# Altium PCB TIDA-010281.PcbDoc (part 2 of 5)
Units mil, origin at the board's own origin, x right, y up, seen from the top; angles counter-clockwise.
Board outline 3455.86 x 1121.8 mil, 8 copper layers (Top Layer, GND1, Sig1, PWR1, PWR2, Sig2, GND2, Bottom Layer), stack 59.155 mil thick; 291 components, 180 nets, 941 pads, 539 vias.
Unrouted connection lines stored in the file: 41.
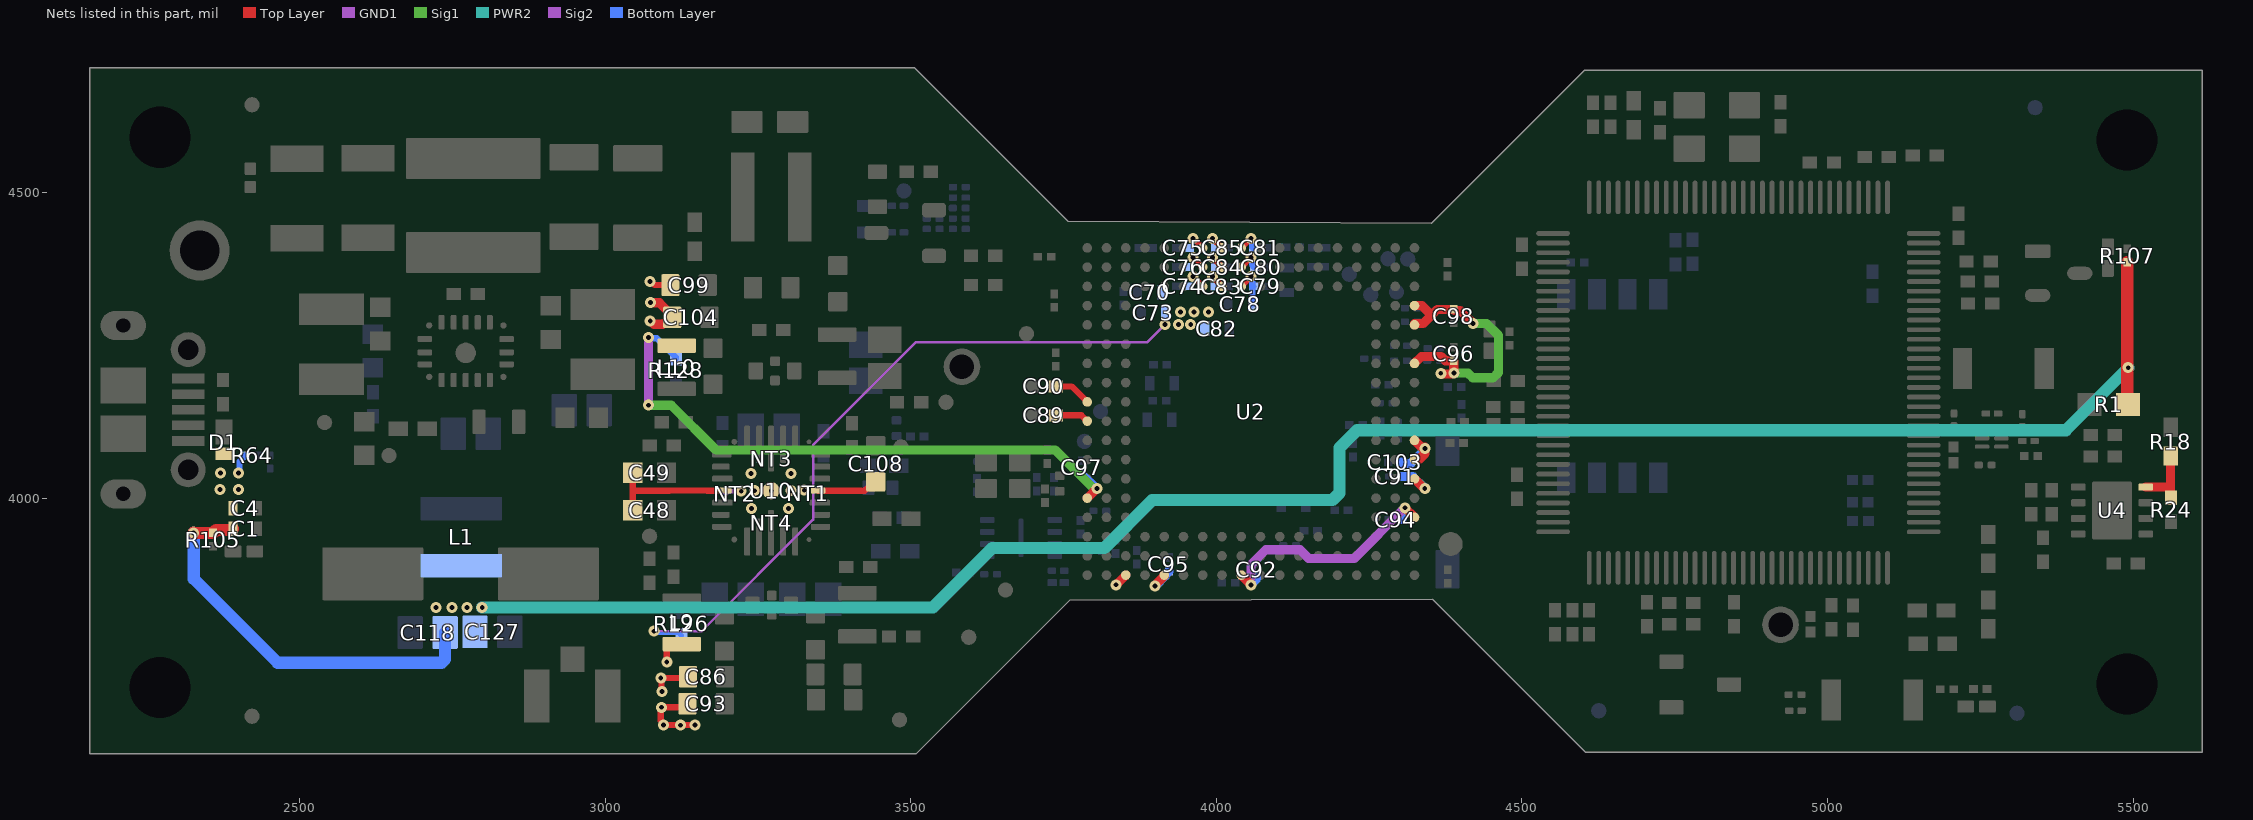
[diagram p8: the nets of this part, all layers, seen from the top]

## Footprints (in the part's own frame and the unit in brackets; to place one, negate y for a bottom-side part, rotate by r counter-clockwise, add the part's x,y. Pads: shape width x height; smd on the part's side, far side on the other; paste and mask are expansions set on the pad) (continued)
FP-4953_HDR1-MFG [mm]
  round 2.5 hole 1.65 paste-1000 mask+0: 1(0,0)
  body extent -1.42,-1.35 1.42,1.35, height 0.25
FP-74438366010_SMT_IND_5MM4_5MM4-MFG [mm]
  rrect6% 1.7x5.6 smd paste+0 mask+0: 1(-1.95,0) 2(1.95,0)
  silkscreen extent -3.47,-2.8 0.72,2.8, body extent -2.7,-2.7 2.7,2.7, height 2.1
FP-885012106005_0603-MFG [mm]
  rrect13% 0.8x0.8 smd paste+0 mask+0: 1(-0.75,0) 2(0.75,0)
  silkscreen extent -0.9,-0.77 0.9,0.77, body extent -1.25,-0.6 1.25,0.6, height 0.25
FP-A767KS336M1KLAE045_RADIAL-MFG [mm]
  rrect5% 4.2x2.2 smd paste+0 mask+0: 1(-3.65,0) 2(3.65,0)
  silkscreen extent -6.42,-4.25 4.25,4.25, body extent -4.5,-4.15 4.5,4.15, height 12.5
FP-ABS05W-32.768KHZ-D-2-T_XTAL_SMT_1MM6_1MM0-MFG [mm]
  rrect20% 0.5x1 smd paste+0 mask+0: 1(-0.55,0) 2(0.55,0)
  body extent -0.8,-0.5 0.8,0.5, height 0.5
FP-BSS123-7-F_SOT23-IPC_C [mm]
  rrect18% 1.059x0.547 smd paste+0 mask+0: 1(-0.877,0.915)
  rrect100% 1.059x0.547 smd paste+0 mask+0: 2(-0.877,-0.915) 3(0.877,0)
  body extent -1.51,-1.55 1.51,1.55, height 0.25
FP-CGA3E1X7R1C105M080AC_0603-IPC_C [mm]
  rrect18% 0.556x1.006 smd paste+0 mask+0: 1(-0.825,0) 2(0.825,0)
  silkscreen extent -0.25,-0.55 0.25,0.55, body extent -0.8,-0.4 0.8,0.4, height 1.1
FP-CHS-01TA_SMT_SW_5MM4_2MM5-MFG [mm]
  rrect10% 1.6x1 smd paste+0 mask+0: 1(-2.54,0) 2(2.54,0)
  body extent -2.8,-1.25 2.8,1.25, height 2.5
FP-CL03A105MO3NRNH_0201-IPC_C [mil]
  rrect33% 15.83x11.94 smd paste+0 mask+0: 1(-9.87,0) 2(9.87,0)
  body extent -12,-6 12,6, height 15
FP-CX2016DB40000D0FLJCC_SMT_2MM0_1MM6-MFG [mm]
  rrect13% 0.9x0.8 smd paste+0 mask+0: 1(-0.7,-0.55) 2(0.7,-0.55) 3(0.7,0.55) 4(-0.7,0.55)
  body extent -1.25,-1.05 1.25,1.05, height 0.25
FP-ECS-160-8-33Q-RES-TR_SMT4_3MM2_2MM5-MFG [mm]
  rrect9% 1.3x1.1 smd paste+0 mask+0: 1(-1.15,-0.9) 2(1.15,-0.9) 3(1.15,0.9) 4(-1.15,0.9)
  silkscreen extent -2.48,-1.3 0.13,1.3, body extent -1.9,-1.55 1.9,1.55, height 0.25
FP-GRM21BD72A225ME01K_0805-IPC_C [mil]
  rrect9% 41.52x53.39 smd paste+0 mask+0: 1(-28.57,0) 2(28.57,0)
  silkscreen extent -49,-44 49,44, body extent -39,-25 39,25, height 57
FP-GRM32EC81C476KE15K_1210-MFG [mm]
  rrect9% 1.1x2.05 smd paste+0 mask+0: 1(-1.65,0) 2(1.65,0)
  silkscreen extent -0.72,-1.35 0.72,1.35, body extent -1.6,-1.25 1.6,1.25, height 2.7
"FP-GRM033R6YA104KE14D_0201 (0603 Metric)-IPC_C" [mil]
  rrect38% 13.94x10.34 smd paste+0 mask+0: 1(-10.01,0) 2(10.01,0)
  body extent -21,-10 21,10, height 10
FP-GRM155R71E104KE14J_0402-IPC_C [mil]
  rrect21% 20.29x18.6 smd paste+0 mask+0: 1(-14.9,0) 2(14.9,0)
  silkscreen extent -25,-27 25,27, body extent -29,-15 29,15, height 10
FP-GRM187R60J226ME15D_0603-MFG [mm]
  rrect13% 0.75x0.9 smd paste+0 mask+0: 1(-0.775,0) 2(0.775,0)
  silkscreen extent 0,-0.5 0,0.5, body extent -1.25,-0.6 1.25,0.6, height 0.25
FP-HCJ0603ZT0R00_0603-MFG [mm]
  rrect11% 1.3x0.92 smd paste+0 mask+0: 1(-0.95,0) 2(0.95,0)
  silkscreen extent -0.9,-0.83 0.9,0.83, body extent -1.7,-0.63 1.7,0.63, height 0.25
FP-NFM18HC105C1C3D_0603-MFG [mm]
  rrect17% 0.6x0.7 smd paste+0 mask+0: 1(-0.8,0) 3(0.8,0)
  rrect25% 0.4x0.4 smd paste+0 mask+0: 2(0,0.4) 2(0,-0.4)
  silkscreen extent -1.78,-0.97 0.85,0.97, body extent -1.2,-0.7 1.2,0.7, height 0.25
"FP-RC0201JR-070RL_0201 (0603 METRIC)-IPC_C" [mil]
  rrect38% 13.94x10.34 smd paste+0 mask+0: 1(-10.01,0) 2(10.01,0)
  body extent -12,-6 12,6, height 10
"FP-RC0201JR-070RL_0201 (0603 Metric)-MFG" [mm]
  rrect29% 0.35x0.4 smd paste+0 mask+0: 1(-0.325,0) 2(0.325,0)
  body extent -0.3,-0.15 0.3,0.15, height 0.26
FP-RC0402FR-0710KL_0402-MFG [mm]
  rrect20% 0.5x0.6 smd paste+0 mask+0: 1(-0.5,0) 2(0.5,0)
  silkscreen extent -0.5,-0.67 0.5,0.67, body extent -0.5,-0.25 0.5,0.25, height 0.4
FP-RR0306P-103-D_0201-IPC_C#1 [mil]
  rrect37% 13.31x10.73 smd paste+0 mask+0: 1(-10.52,0) 2(10.52,0)
  body extent -12,-6 12,6, height 10
FP-RR0306P-103-D_0201-IPC_C#2 [mil]
  rrect38% 13.94x10.34 smd paste+0 mask+0: 1(-10.52,0)
  rrect37% 13.31x10.73 smd paste+0 mask+0: 2(10.52,0)
  body extent -12,-6 12,6, height 10
FP-XGL4030-152MEC_SMT2_4MM0_4MM0-MFG [mm]
  rrect10% 0.98x3.4 smd paste+0 mask+0: 1(-1.185,0) 2(1.185,0)
  silkscreen extent -2.75,-2.15 2.15,2.15, body extent -2,-2 2,2, height 3.1
MHNP_2-5 [mil]
  round 95 hole 100 unplated mask+5.5: ""(0,0)
  Keep-Out Layer circle w1: c0,0 r100
Net-Tie_50milWide_30milLong [mil] "50mil net tie, no solder mask opening, no solder paste"
  rect 30x50 on Mid1 paste-20 mask-20: 1(-15,0) 2(15,0)
PDT0128A [mm] "Thin QFP, 128-Leads, Body 14x14mm, Pitch 0.4mm"
  oval 1.4x0.2 smd: 1(-7.7,6.2) 2(-7.7,5.8) 3(-7.7,5.4) 4(-7.7,5) 5(-7.7,4.6) 6(-7.7,4.2) 7(-7.7,3.8) 8(-7.7,3.4) 9(-7.7,3) 10(-7.7,2.6) 11(-7.7,2.2) 12(-7.7,1.8) 13(-7.7,1.4) 14(-7.7,1) 15(-7.7,0.6) 16(-7.7,0.2) 17(-7.7,-0.2) 18(-7.7,-0.6) 19(-7.7,-1) 20(-7.7,-1.4) 21(-7.7,-1.8) 22(-7.7,-2.2) 23(-7.7,-2.6) 24(-7.7,-3) 25(-7.7,-3.4) 26(-7.7,-3.8) 27(-7.7,-4.2) 28(-7.7,-4.6) 29(-7.7,-5) 30(-7.7,-5.4) 31(-7.7,-5.8) 32(-7.7,-6.2) 65(7.7,-6.2) 66(7.7,-5.8) 67(7.7,-5.4) 68(7.7,-5) 69(7.7,-4.6) 70(7.7,-4.2) 71(7.7,-3.8) 72(7.7,-3.4) 73(7.7,-3) 74(7.7,-2.6) 75(7.7,-2.2) 76(7.7,-1.8) 77(7.7,-1.4) 78(7.7,-1) 79(7.7,-0.6) 80(7.7,-0.2) 81(7.7,0.2) 82(7.7,0.6) 83(7.7,1) 84(7.7,1.4) 85(7.7,1.8) 86(7.7,2.2) 87(7.7,2.6) 88(7.7,3) 89(7.7,3.4) 90(7.7,3.8) 91(7.7,4.2) 92(7.7,4.6) 93(7.7,5) 94(7.7,5.4) 95(7.7,5.8) 96(7.7,6.2)
  oval 0.2x1.4 smd: 33(-6.2,-7.7) 34(-5.8,-7.7) 35(-5.4,-7.7) 36(-5,-7.7) 37(-4.6,-7.7) 38(-4.2,-7.7) 39(-3.8,-7.7) 40(-3.4,-7.7) 41(-3,-7.7) 42(-2.6,-7.7) 43(-2.2,-7.7) 44(-1.8,-7.7) 45(-1.4,-7.7) 46(-1,-7.7) 47(-0.6,-7.7) 48(-0.2,-7.7) 49(0.2,-7.7) 50(0.6,-7.7) 51(1,-7.7) 52(1.4,-7.7) 53(1.8,-7.7) 54(2.2,-7.7) 55(2.6,-7.7) 56(3,-7.7) 57(3.4,-7.7) 58(3.8,-7.7) 59(4.2,-7.7) 60(4.6,-7.7) 61(5,-7.7) 62(5.4,-7.7) 63(5.8,-7.7) 64(6.2,-7.7) 97(6.2,7.7) 98(5.8,7.7) 99(5.4,7.7) 100(5,7.7) 101(4.6,7.7) 102(4.2,7.7) 103(3.8,7.7) 104(3.4,7.7) 105(3,7.7) 106(2.6,7.7) 107(2.2,7.7) 108(1.8,7.7) 109(1.4,7.7) 110(1,7.7) 111(0.6,7.7) 112(0.2,7.7) 113(-0.2,7.7) 114(-0.6,7.7) 115(-1,7.7) 116(-1.4,7.7) 117(-1.8,7.7) 118(-2.2,7.7) 119(-2.6,7.7) 120(-3,7.7) 121(-3.4,7.7) 122(-3.8,7.7) 123(-4.2,7.7) 124(-4.6,7.7) 125(-5,7.7) 126(-5.4,7.7) 127(-5.8,7.7) 128(-6.2,7.7)
  silkscreen extent -7.7,-6.3 6.3,6.99, body extent -8,-8 8,8, height 1.07
RXV0028A-MFG [mm]
  round 0.195 smd paste+0 mask+0: 1(-1.573,2.03) 9(-1.573,-2.03)
  rrect40% 0.8x0.25 smd paste+0 mask+0: 2(-2.05,1.5) 8(-2.05,-1.5) 16(2.05,-1.5) 22(2.05,1.5)
  rrect40% 0.725x0.25 smd paste+0 mask+0: 3(-2.087,1) 7(-2.087,-1) 17(2.087,-1) 21(2.087,1)
  rrect40% 0.85x0.25 smd paste+0 mask+0: 4(-2.025,0.5) 6(-2.025,-0.5) 18(2.025,-0.5) 20(2.025,0.5)
  rrect40% 0.6x0.25 smd paste+0 mask+0: 5(-1.95,0) 19(1.95,0)
  round 0.72 smd paste-1000 mask+0: 5-19(0,0)
  rrect40% 0.25x1.175 smd paste+0 mask+0: 10(-1,-2.113) 14(1,-2.113) 24(1,2.113) 28(-1,2.113)
  rrect40% 0.25x1.55 smd paste-1000 mask+0: 11(-0.5,-1.925) 13(0.5,-1.925) 25(0.5,1.925) 27(-0.5,1.925)
  rrect40% 0.25x1.9 smd paste-1000 mask+0: 12(0,-1.75) 26(0,1.75)
  round 0.243 smd paste+0 mask+0: 15(1.53,-2.03) 23(1.53,2.03)
  Top Layer region: -2.45,2.075 -2.443,2.1 -2.425,2.118 -2.4,2.125 -2.4,2.125 -1.625,2.125 -1.625,2.65 -1.618,2.675 -1.6,2.693 -1.575,2.7 -1.575,2.7 -1.425,2.7 -1.406,2.696 -1.39,2.685 -1.379,2.669 -1.375,2.65 -1.375,2.65 -1.375,1.925 -1.379,1.906 -1.39,1.89 -1.406,1.879 -1.425,1.875 -1.425,1.875 -2.4,1.875 -2.419,1.879 -2.435,1.89 -2.446,1.906 -2.45,1.925 -2.45,1.925
  Top Layer region: -2.45,-2.075 -2.443,-2.1 -2.425,-2.118 -2.4,-2.125 -2.4,-2.125 -1.625,-2.125 -1.625,-2.65 -1.618,-2.675 -1.6,-2.693 -1.575,-2.7 -1.575,-2.7 -1.425,-2.7 -1.406,-2.696 -1.39,-2.685 -1.379,-2.669 -1.375,-2.65 -1.375,-2.65 -1.375,-1.925 -1.379,-1.906 -1.39,-1.89 -1.406,-1.879 -1.425,-1.875 -1.425,-1.875 -2.4,-1.875 -2.419,-1.879 -2.435,-1.89 -2.446,-1.906 -2.45,-1.925 -2.45,-1.925
  Top Layer region: 2.45,-2.075 2.443,-2.1 2.425,-2.118 2.4,-2.125 2.4,-2.125 1.625,-2.125 1.625,-2.65 1.618,-2.675 1.6,-2.693 1.575,-2.7 1.575,-2.7 1.425,-2.7 1.4,-2.693 1.382,-2.675 1.375,-2.65 1.375,-2.65 1.375,-1.925 1.379,-1.906 1.39,-1.89 1.406,-1.879 1.425,-1.875 1.425,-1.875 2.4,-1.875 2.419,-1.879 2.435,-1.89 2.446,-1.906 2.45,-1.925 2.45,-1.925
  Top Layer region: 2.45,2.075 2.443,2.1 2.425,2.118 2.4,2.125 2.4,2.125 1.625,2.125 1.625,2.65 1.618,2.675 1.6,2.693 1.575,2.7 1.575,2.7 1.425,2.7 1.4,2.693 1.382,2.675 1.375,2.65 1.375,2.65 1.375,1.925 1.379,1.906 1.39,1.89 1.406,1.879 1.425,1.875 1.425,1.875 2.4,1.875 2.419,1.879 2.435,1.89 2.446,1.906 2.45,1.925 2.45,1.925
  Top Layer region: -2.45,0.075 -2.443,0.1 -2.425,0.118 -2.4,0.125 -2.4,0.125 -0.625,0.125 -0.625,0.4 0.625,0.4 0.625,0.125 2.4,0.125 2.425,0.118 2.443,0.1 2.45,0.075 2.45,0.075 2.45,-0.075 2.443,-0.1 2.425,-0.118 2.4,-0.125 2.4,-0.125 0.625,-0.125 0.625,-0.4 -0.625,-0.4 -0.625,-0.125 -2.4,-0.125 -2.425,-0.118 -2.443,-0.1 -2.45,-0.075 -2.45,-0.075
  silkscreen extent -3.13,-3.1 2.3,3.1, body extent -2.25,-2.5 2.25,2.5, height 1
RZT0020A-MFG [mm]
  round 0.259 smd paste+0 mask+0: 1(-1.069,1.519) 7(-1.069,-1.569) 11(1.069,-1.569) 17(1.069,1.519)
  rrect40% 0.6x0.25 smd paste+0 mask+0: 2(-1.2,1) 3(-1.2,0.5) 4(-1.2,0) 5(-1.2,-0.5) 6(-1.2,-1) 12(1.2,-1) 13(1.2,-0.5) 14(1.2,0) 15(1.2,0.5) 16(1.2,1)
  rrect40% 0.25x0.6 smd paste+0 mask+0: 8(-0.55,-1.7) 9(-0.05,-1.7) 10(0.5,-1.7) 18(0.5,1.7) 19(-0.05,1.7) 20(-0.55,1.7)
  round 0.855 smd paste-1000 mask+0: 21(-0.075,0)
  Top Layer region: -1.45,1.375 -1.469,1.379 -1.485,1.39 -1.496,1.406 -1.5,1.425 -1.5,1.425 -1.5,1.575 -1.493,1.6 -1.475,1.618 -1.45,1.625 -1.45,1.625 -1.275,1.625 -1.237,1.633 -1.204,1.654 -1.183,1.687 -1.175,1.725 -1.175,1.725 -1.175,1.95 -1.168,1.975 -1.15,1.993 -1.125,2 -1.125,2 -0.975,2 -0.956,1.996 -0.94,1.985 -0.929,1.969 -0.925,1.95 -0.925,1.95 -0.925,1.425 -0.929,1.406 -0.94,1.39 -0.956,1.379 -0.975,1.375 -0.975,1.375
  Top Layer region: -1.45,-1.375 -1.469,-1.379 -1.485,-1.39 -1.496,-1.406 -1.5,-1.425 -1.5,-1.425 -1.5,-1.575 -1.496,-1.594 -1.485,-1.61 -1.469,-1.621 -1.45,-1.625 -1.45,-1.625 -1.275,-1.625 -1.237,-1.633 -1.204,-1.654 -1.183,-1.687 -1.175,-1.725 -1.175,-1.725 -1.175,-1.95 -1.171,-1.969 -1.16,-1.985 -1.144,-1.996 -1.125,-2 -1.125,-2 -0.975,-2 -0.956,-1.996 -0.94,-1.985 -0.929,-1.969 -0.925,-1.95 -0.925,-1.95 -0.925,-1.425 -0.929,-1.406 -0.94,-1.39 -0.956,-1.379 -0.975,-1.375 -0.975,-1.375
  Top Layer region: 1.45,-1.375 1.469,-1.379 1.485,-1.39 1.496,-1.406 1.5,-1.425 1.5,-1.425 1.5,-1.575 1.496,-1.594 1.485,-1.61 1.469,-1.621 1.45,-1.625 1.45,-1.625 1.275,-1.625 1.237,-1.633 1.204,-1.654 1.183,-1.687 1.175,-1.725 1.175,-1.725 1.175,-1.95 1.171,-1.969 1.16,-1.985 1.144,-1.996 1.125,-2 1.125,-2 0.975,-2 0.956,-1.996 0.94,-1.985 0.929,-1.969 0.925,-1.95 0.925,-1.95 0.925,-1.425 0.929,-1.406 0.94,-1.39 0.956,-1.379 0.975,-1.375 0.975,-1.375
  Top Layer region: 1.45,1.375 1.469,1.379 1.485,1.39 1.496,1.406 1.5,1.425 1.5,1.425 1.5,1.575 1.496,1.594 1.485,1.61 1.469,1.621 1.45,1.625 1.45,1.625 1.275,1.625 1.237,1.633 1.204,1.654 1.183,1.687 1.175,1.725 1.175,1.725 1.175,1.95 1.171,1.969 1.16,1.985 1.144,1.996 1.125,2 1.125,2 0.975,2 0.956,1.996 0.94,1.985 0.929,1.969 0.925,1.95 0.925,1.95 0.925,1.425 0.929,1.406 0.94,1.39 0.956,1.379 0.975,1.375 0.975,1.375
  Top Layer region: -0.55,1 -0.543,1.025 -0.525,1.043 -0.5,1.05 -0.5,1.05 0.099,1.05 0.124,1.044 0.142,1.026 0.149,1.001 0.149,1.001 0.178,0.897 0.252,0.819 0.354,0.785 0.354,0.785 0.377,0.777 0.394,0.759 0.4,0.735 0.4,0.735 0.4,-0.735 0.394,-0.759 0.377,-0.777 0.354,-0.785 0.354,-0.785 0.252,-0.819 0.178,-0.897 0.149,-1.001 0.149,-1.001 0.142,-1.026 0.124,-1.044 0.099,-1.05 0.099,-1.05 -0.249,-1.05 -0.274,-1.044 -0.292,-1.026 -0.299,-1.001 -0.299,-1.001 -0.328,-0.897 -0.402,-0.819 -0.504,-0.785 -0.504,-0.785 -0.527,-0.777 -0.544,-0.759 -0.55,-0.735 -0.55,-0.735
  silkscreen extent -2.17,-2.22 1.73,2.22, body extent -1.3,-1.8 1.3,1.8, height 0.7
SOT-23 [mm] "SOT23, 3-Leads, Body 2.9x1.3mm, Pitch 0.95mm, Lead Span 2.5mm, IPC Medium Density"
  rrect50% 1x0.6 smd: 1(-1.2,0.95) 2(-1.2,-0.95) 3(1.2,0)
  silkscreen extent -1.62,-1.5 0.7,1.5, body extent -1.16,-1.45 1.21,1.45, height 1
SW_218-4LPST [mil] "CTS Components"
  rect 50x30 smd: 1(-150,75) 2(-150,25) 3(-150,-25) 4(-150,-75) 5(150,-75) 6(150,-25) 7(150,25) 8(150,75)
  silkscreen extent -114,-123 114,123, body extent -166,-123 166,123, height 104
SW_B3U-1000P [mm] "OMRON"
  rect 0.8x1.7 smd: 1(-1.7,0) 2(1.7,0)
  silkscreen extent -1.5,-1.25 1.5,1.25, body extent -1.5,-1.25 1.5,1.25, height 1.75
TFM201610ALMA [mm] "TDK"
  rrect17% 0.6x1.6 smd: 1(-0.9,0) 2(0.9,0)
  body extent -1.1,-0.9 1.1,0.9, height 1
TLMx1000_Yellow [mm] "SMD, 2-Leads, Body 1.6x0.8mm"
  rrect17% 0.6x0.8 smd: 1(-0.725,0) 2(0.725,0)
  silkscreen extent -0.97,-0.8 1.6,0.8, body extent -0.85,-0.45 0.85,0.45, height 0.65
TP_25MIL-SMT#1 [mil]
  round 25 smd mask-2.5: 1(0,0)
TP_25MIL-SMT#2 [mil]
  round 25 smd mask-2.5: 1(-10,0)
TP_SM_1MM [mm] "1mm Test Point, SMT"
  round 1 smd paste-0.5: 1(0,0)
TP_VIA_060RND040 [mil] "TP_VIA_060RND040"
  round 60 hole 40: 1(0,0)
USON-8L [mm] "SON, 8-Leads, Body 3x2mm, Pitch 0.5mm"
  rrect40% 0.6x0.25 smd: 1(-1.4,0.75) 2(-1.4,0.25) 3(-1.4,-0.25) 4(-1.4,-0.75) 5(1.4,-0.75) 6(1.4,-0.25) 7(1.4,0.25) 8(1.4,0.75)
  rrect50% 0.2x1.6 smd: 9(0,0)
  silkscreen extent -1.55,-1.17 0.65,1.17, body extent -1.55,-1.05 1.55,1.05, height 0.6
WE-MAPI_4030 [mm] "SMT Shielded Power Inductor, body 4.1x4.1mm"
  rect 0.98x3.7 smd: 1(-1.185,0) 2(1.185,0)
  Top Layer keep-out region: -0.595,2.05 0.595,2.05 0.595,-2.05 -0.595,-2.05
  silkscreen extent -2.15,-2.15 2.15,2.7, body extent -2.05,-2.05 2.05,2.05, height 3.1

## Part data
C1 C4 C55 C59 C62 C65 C70 C73 C78 C82: library part CMP-0006339-4, "CAP, CERM, 10 uF, 10 V, +/- 20%, X5R, 0402", Cap_Case=0402, Manufacturer="Samsung Electro-Mechanics", TempCo=X5R, Tolerance_%=20%, Value1=Unknown, Value2=10V, ValueDisplayed=10uF
C5 C13 C17: library part CMP-0006302-2, "CAP, CERM, 2.2 uF, 10 V, +/- 10%, X7S, 0402", Cap_Case=0402_065, Manufacturer=TDK, Supplier Part Number 1=445-9097-1-ND, TempCo=X7S, Tolerance_%=10%, Value1="0.005925 ohm", Value2=10V, ValueDisplayed=2.2uF
C6 C7 C8 C10 C18 C19 C21 C22 C25: library part CMP-0078241-1, "CAP, CERM, 0.1 µF, 10 V,+/- 10%, X7R, 0402", Cap_Case=0402, Manufacturer=Kemet, Supplier Part Number 1=399-3520-1-ND, TempCo=X7R, Tolerance_%=10%, Value2=10V, ValueDisplayed=0.1µF
C9 C16 C26: library part CMP-0006352-2, "CAP, CERM, 0.01 uF, 25 V, +/- 10%, X7R, 0402", Cap_Case=0402, Manufacturer=MuRata, Supplier Part Number 1=490-6043-2-ND, TempCo=X7R, Tolerance_%=10%, Value1=Unknown, Value2=25V, ValueDisplayed=0.01uF
C11 C12 C20: library part CMP-0006272-2, "CAP, CERM, 1 uF, 10 V, +/- 10%, X6S, 0402", Cap_Case=0402, Manufacturer=TDK, Supplier Part Number 1=445-4978-1-ND, TempCo=X5R, Tolerance_%=10%, Value1=Unknown, Value2=16V, ValueDisplayed=1uF
C14 C71: library part CMP-0080076-1, "CAP, CERM, 4.7 pF, 50 V,+/- 3%, C0G/NP0, 0201", Cap_Case=0201, Manufacturer=MuRata, Supplier Part Number 1=490-11332-1-ND, TempCo=C0G/NP0, Tolerance_%=3%, Value2=50V, ValueDisplayed=4.7pF
C15: library part CMP-0078217-1, "CAP, CERM, 15 pF, 50 V,+/- 1%, C0G/NP0, 0402", Cap_Case=0402, Manufacturer=AVX, Supplier Part Number 1=478-5126-1-ND, TempCo=C0G/NP0, Tolerance_%=1%, Value2=50V, ValueDisplayed=15pF
C23 C24: library part CMP-0860185-1, "CAP, CERM, 8 pF, 50 V,+/- 6.25%, C0G/NP0, 0402", Cap_Case=0402, Manufacturer=Yageo, TempCo=C0G/NP0, Tolerance_%=6.25%, Value2=50V, ValueDisplayed=8pF
C27 C54 C77 C86 C93 C99 C104: library part CMP-0090352-1, "22µF ±20% 6.3V Ceramic Capacitor X5R 0603 (1608 Metric)", Digikey Part Number=490-13242-1-ND, Manufacturer=Murata, Mouser Part Number=81-GRM187R60J226ME5D, Operating Temperature Range="-55°C to +85°C", TempCo=15%, Temperature Characteristic=X5R, Tolerance_%=20%, ValueDisplayed=22uF
C28 C29 C35 C105 C108: library part CMP-0049191-1, "4.7 µF ±20% 6.3V Ceramic Capacitor X5R 0603 (1608 Metric)", Digikey Part Number=732-7902-1-ND, Manufacturer="Wurth Electronics", Mouser Part Number=710-885012106005, Operating Temperature Range="-55°C to +85°C", TempCo=15%, Temperature Characteristic=X5R, Tolerance_%=20%, ValueDisplayed=4.7uF
C36: library part CMP-0006542-2, "CAP, CERM, 0.22 uF, 6.3 V, +/- 10%, X5R, 0402", Cap_Case=0402, Manufacturer=MuRata, Supplier Part Number 1=490-5407-1-ND, TempCo=X5R, Tolerance_%=10%, Value1=Unknown, Value2=6.3V, ValueDisplayed=0.22uF
C37: library part CMP-0006351-2, "CAP, CERM, 0.1 uF, 16 V, +/- 10%, X7R, 0402", Cap_Case=0402, Manufacturer=MuRata, Supplier Part Number 1=490-4759-2-ND, TempCo=X7R, Tolerance_%=10%, Value1=Unknown, Value2=16V, ValueDisplayed=0.1uF
C38 C39: library part CMP-0087190-1, "CAP CER 12PF 25V C0G/NP0 0201", Manufacturer="Johanson Technology Inc.", TempCo=30ppm/°C, Tolerance_%=5%
C40 C41 C42 C106 C107: library part CMP-0008017-2, "CAP, CERM, 10 uF, 10 V, +/- 10%, X7R, 0805", Cap_Case=0805, Manufacturer=MuRata, Supplier Part Number 1=490-10674-1-ND, TempCo=X7R, Tolerance_%=10%, Value1=Unknown, Value2=10V, ValueDisplayed=10uF
C43 C137: library part CMP-0088247-2, "3 Terminals Low ESL Chip Multilayer Ceramic Capacitors for Automotive", Manufacturer=Murata, Tolerance_%=20%, ValueDisplayed=1uF
C48 C49: library part CMP-0007134-5, "CAP, CERM, 2.2 uF, 6.3 V, +/- 10%, X7R, AEC-Q200 Grade 1, 0603", Cap_Case=0603, Manufacturer=MuRata, Supplier Part Number 1=490-5316-1-ND, TempCo=X7R, Tolerance_%=10%, Value1=Unknown, Value2=6.3V, ValueDisplayed=2.2uF
C56 C57 C58 C60 C61 C63 C64 C66 C67 C68 C75 C76 C80 C81 C84 C85 C87 C88 C94 C95 C96 C97 C98: library part CMP-0009781-1, "CAP, CERM, 0.22 uF, 10 V, +/- 20%, X5R, 0201", Cap_Case=0201, Manufacturer="Taiyo Yuden", Supplier Part Number 1=587-2483-1-ND, TempCo=X5R, Tolerance_%=20%, Value1=Unknown, Value2=10V, ValueDisplayed=0.22uF
C69: library part CMP-0009718-2, "CAP, CERM, 0.047 uF, 16 V, +/- 10%, X5R, 0201", Cap_Case=0201, Manufacturer=MuRata, Supplier Part Number 1=490-7227-1-ND, TempCo=X5R, Tolerance_%=10%, Value1=Unknown, Value2=16V, ValueDisplayed=0.047uF
C72 C91 C92 C101 C120 C130: library part CMP-0086440-1, "Cap Ceramic 0.1uF 35V X5R 10% Pad SMD 0201 85C T/R", Manufacturer="Murata Electronics North America", TempCo=15%, Tolerance_%=10%
C74 C79 C83 C102 C103: library part CMP-0009657-3, "CAP, CERM, 2.2 uF, 6.3 V, +/- 20%, X5R, 0201", Cap_Case=0201, Manufacturer="Samsung Electro-Mechanics", TempCo=X5R, Tolerance_%=20%, Value1=Unknown, Value2=6.3V, ValueDisplayed=2.2uF
C89 C90: library part CMP-0081763-1, "CAP, CERM, 1 µF, 6.3 V,+/- 10%, X6S, 0402", Cap_Case=0402, Manufacturer=TDK, Supplier Part Number 1=445-13189-1-ND, TempCo=X6S, Tolerance_%=10%, Value2=6.3V, ValueDisplayed=1µF
C100: library part CMP-0086446-1, "1µF ±20% 16V Ceramic Capacitor X5R 0201", Manufacturer="Samsung Electro-Mechanics", TempCo=15%, Tolerance_%=20%
C116: library part CMP-0095369-1, "Cap Ceramic 1uF 16V X7R 20% Pad SMD 0603 +125°C Automotive T/R", Manufacturer=TDK, Operating Temperature Range="-55°C to +125°C", Part Number=CGA3E1X7R1C105M080AC, TempCo=0.15, Temperature Characteristic=X7R, Tolerance_%=0.2%, ValueDisplayed=1uF
C117: library part CMP-0006295-2, "CAP, CERM, 0.1 uF, 25 V, +/- 20%, X7R, 0402", Cap_Case=0402, Manufacturer=TDK, PartNumber=C1005X7R1E104M050BB, Supplier Part Number 1=445-7349-1-ND, TempCo=X7R, Tolerance_%=20%, Value1=Unknown, Value2=25V, ValueDisplayed=0.1uF
C118 C119 C127 C128: library part CMP-0096278-1, "Chip Multilayer Ceramic Capacitor for General Purpose 2.2uF ±20% 100V X7T SMD 0805", Digikey Part Number=490-GRM21BD72A225ME01KCT-ND, Manufacturer=Murata, Mouser Part Number=81-GRM21BD72A225ME1K, Operating Temperature Range="-55°C to +125°C", TempCo=+22/-33%, Temperature Characteristic=X7T, Tolerance_%=20%, ValueDisplayed=2.2uF
C122 C123: library part CMP-0081011-1, "CAP, CERM, 0.1 µF, 100 V,+/- 10%, X7R, AEC-Q200 Grade 1, 0603", Cap_Case=0603, Manufacturer="Taiyo Yuden", Supplier Part Number 1=587-6009-1-ND, TempCo=X7R, Tolerance_%=10%, Value2=100V, ValueDisplayed=0.1µF
C124 C125: library part CMP-0009150-2, "CAP, CERM, 4.7 uF, 100 V, +/- 10%, X7S, AEC-Q200 Grade 1, 1210", Cap_Case=1210_220, Manufacturer=TDK, Supplier Part Number 1=445-7005-1-ND, TempCo=X7S, Tolerance_%=10%, Value1="0.004236 ohm", Value2=100V, ValueDisplayed=4.7uF
C129: library part CMP-0096303-1, "33 µF 80 V Aluminum - Polymer Capacitors Radial, Can - SMD 45mOhm 2000 Hrs @ 105°C", Digikey Part Number=399-15650-1-ND, Leakage Current=528uA, Manufacturer=KEMET, Mouser Part Number=80-A767KS336M1KLAE45, Operating Temperature Range="-55°C to +105°C", Tolerance_%=20%, ValueDisplayed=33uF
C131 C135: library part CMP-0009154-2, "CAP, CERM, 22 uF, 16 V, +/- 20%, X7R, AEC-Q200 Grade 1, 1210", Cap_Case=1210_280, Manufacturer=TDK, Supplier Part Number 1=445-5723-1-ND, TempCo=X7R, Tolerance_%=20%, Value1="0.002582 ohm", Value2=16V, ValueDisplayed=22uF
C132: library part CMP-0095279-1, "Chip Multilayer Ceramic Capacitors for General Purpose, 0402, 0.10uF, X7R, 15%, 10%, 25V", Manufacturer=Murata, Operating Temperature Range="-55°C to +125°C", Part Number=GRM155R71E104KE14J, TempCo=15%, Temperature Characteristic=X7R, Tolerance_%=10%, ValueDisplayed=0.10uF
C133 C134: library part CMP-0095373-1, "Chip Multilayer Ceramic Capacitors for General Purpose, 1210, 47uF, X6S, 22%, 10%, 16V", Manufacturer=Murata, Operating Temperature Range="-55°C to +105°C", TempCo=22%, Temperature Characteristic=X6S, Tolerance_%=10%, ValueDisplayed=47uF
C136: library part CMP-0006753-4, "CAP, CERM, 0.1 uF, 25 V, +/- 10%, X7R, 0603", Cap_Case=0603, Manufacturer=AVX, PartNumber=06033C104KAT2A, Supplier Part Number 1=478-3714-1-ND, TempCo=X7R, Tolerance_%=10%, Value1="0.05 ohm", Value2=25V, ValueDisplayed=0.1uF
D1: library part CMP-0028829-2, "Diode, Schottky, 30 V, 2 A, 2-XFDFN", Manufacturer="ON Semiconductor", Value1=2A, Value2=0.48V
D2: library part CMP-0078196-2, "LED, Yellow, SMD", Color=yellow, Manufacturer=Vishay-Semiconductor, Power_TotalModule=40mW, Value1=.04W, Value2=1.8V
FID1 FID2 FID3 FID4 FID5 FID6: library part CMP-0077181-1, "Fiducial mark.  There is nothing to buy or mount.", Manufacturer=N/A
FL2 L12: library part CMP-0078934-1, "Inductor, Ferrite Bead, Ferrite, 2.2 A, 0.035 ohm, AEC-Q200 Grade 1, SMD", Manufacturer=MuRata, Supplier Part Number 1=490-16506-1-ND, Value1="0.035 ohm", Value2=2.2A
J1: library part CMP-0055293-1, "Connector, Receptacle, Micro-USB Type B, R/A, Bottom Mount SMT", Manufacturer=Molex, Supplier Part Number 1=WM1399CT-ND
J9: library part CMP-0075320-1, "Receptacle, Ultra Miniature Coaxial, Male Pin, 50 ohm, SMT", Color=Beige, Manufacturer="Hirose Electric Co. Ltd.", Supplier Part Number 1=H122041-ND
L1: library part CMP-0092596-1, "Shielded Power Inductors 1.5 µH 10.2A 10.5mOhm Max Nonstandard", Digikey Part Number=2457-XGL4030-152MEC-ND, Manufacturer=Coilcraft, Operating Temperature Range=to, Self Resonant Frequency=50MHz, Test Frequency=1MHz, Tolerance_%=20%
L6: library part CMP-0095717-1, "1 µH Shielded - Inductor 7.8 A 13.1mOhm Max Nonstandard", Digikey Part Number=732-74438366010CT-ND, Manufacturer="Wurth Electronics", Mouser Part Number=710-74438366010, Operating Temperature Range="-40°C to +125°C", Self Resonant Frequency=50MHz, Test Frequency=100kHz, Tolerance_%=20%
L7 L9 L10: library part CMP-0081095-1, "Inductor, Shielded, Metal Composite, 470 nH, 3.9 A, 0.039 ohm, AEC-Q200 Grade 0, SMD", Manufacturer=TDK, Supplier Part Number 1=445-174573-1-ND, Value1="0.039 ohm", Value2=3.9A, ValueDisplayed=470nH
L8: library part CMP-0099162-1, "WE-MAPI SMT Power Inductor, size 4030, 4.7uH, 3.9A, 44mOhm", Case/Size Code=4030, DC Resistance=39.9mOhm, DC Resistance Max=44mOhm, Inductance=4.7uH, Manufacturer="Wurth Elektronik", Operating Temperature Max=125°C, Operating Temperature Min=-40°C, Rated Current=3.9A, Saturation Current=6.4A, Self Resonant Frequency=24MHz
L11: library part CMP-0081093-1, "Inductor, Shielded, Metal Composite, 1.5 µH, 2.3 A, 0.11 ohm, AEC-Q200 Grade 0, SMD", Manufacturer=TDK, Supplier Part Number 1=445-174575-1-ND, Value1="0.11 ohm", Value2=2.3A, ValueDisplayed=1.5µH
LD1 LD2 LD3 LD5: library part CMP-0067682-2, "LED, Green, SMD", Color=Green, Manufacturer=Kingbright, Power_TotalModule=75mW, Value1=0.075W, Value2=2.1V
NT1 NT2 NT3: library part CMP-0078142-3, "Single point connection between nets.", Manufacturer=N/A
NT4: library part CMP-0078142-4, "Single point connection between nets.", Manufacturer=N/A
Q1: library part CMP-0087176-1, "MOSFET N-CH 100V 170MA SOT23-3", Manufacturer="Diodes Incorporated"
Q2: library part CMP-0000947-2, "MOSFET, N-CH, 100 V, 0.17 A, SOT-23", Alternate Manufacturer=None, Manufacturer="Fairchild Semiconductor", Supplier Part Number 1=BSS123NCT-ND, Value1=1, Value2="1.8 nC"
R1: library part CMP-0025884-3, "RES, 0, 5%, 0.125 W, 0603", Manufacturer=Vishay/Beyschlag, Power_W=125mW, Supplier Part Number 1=MCT0603-0.0-ZZCT-ND, TempCo=ppm/C, Tolerance_%=5%, Value2=0.125W, Value_Code=0000, ValueDisplayed=0
R2 R103 R109 R118 R129: library part CMP-0086442-2, "RES SMD 0 OHM JUMPER 1/20W 0201", Manufacturer=Yageo, Power_W=50mW, TempCo=200ppm/°C, Tolerance_%=5%
R3 R21 R22 R23 R43 R44 R45 R59 R65 R77 R78 R80 R81 R82 R83 R84 R85 R93 R96 R98 R124 R125 R177 R178: library part CMP-0088002-1, "10 kOhms ±0.5% 0.05W, 1/20W Chip Resistor 0201 (0603 Metric)  Thin Film", Manufacturer=Susumu, Power_W=50mW, TempCo=25ppm/°C, Tolerance_%=0.5%
R4 R5 R9 R119: library part CMP-0027261-3, "RES, 100 k, 1%, 0.05 W, 0201", Manufacturer=Vishay-Dale, Power_W=50mW, Supplier Part Number 1=541-100KAABCT-ND, TempCo="100 ppm/C", Tolerance_%=1%, Value2=0.05W, Value_Code=100k
R6 R46 R47 R48 R49 R66 R67 R69 R70: library part CMP-0027275-3, "RES, 33.2, 1%, 0.05 W, 0201", Manufacturer=Vishay-Dale, Power_W=50mW, Supplier Part Number 1=541-33.2ABCT-ND, TempCo="200 ppm/C", Tolerance_%=1%, Value2=0.05W, Value_Code=33R2, ValueDisplayed=33.2
R13 R42 R111: library part CMP-0027072-1, "RES, 220, 5%, 0.05 W, 0201", Manufacturer="Yageo America", Power_W=50mW, Supplier Part Number 1=311-220NCT-ND, TempCo="200 ppm/C", Tolerance_%=5%, Value2=0.05W, Value_Code=220R, ValueDisplayed=220
R16 R174 R176: library part CMP-0027880-1, "RES, 7.87 k, 1%, 0.05 W, 0201", Manufacturer="Yageo America", Power_W=50mW, Supplier Part Number 1=YAG2807CT-ND, TempCo="200 ppm/C", Tolerance_%=1%, Value2=0.05W, Value_Code=7k87, ValueDisplayed=7.87k
R17 R29: library part CMP-0078210-2, "RES, 330 k, 1%, 0.063 W, AEC-Q200 Grade 0, 0402", Manufacturer=Vishay-Dale, Power_W=63mW, Supplier Part Number 1=541-330KLCT-ND, TempCo="100 ppm/C", Tolerance_%=1%, Value2=0.063W, Value_Code=330k
R18 R30 R38 R51 R57 R63 R91 R92 R94 R115 R121 R126 R127 R128 R131 R134 R136: library part CMP-0026992-3, "RES, 0, 5%, 0.1 W, AEC-Q200 Grade 0, 0402", Manufacturer=Panasonic, Power_W=100mW, Supplier Part Number 1=P0.0JCT-ND, TempCo="600 ppm/C", Tolerance_%=5%, Value2=0.1W, Value_Code=0000, ValueDisplayed=0
R20: library part CMP-0026403-2, "RES, 49.9 k, 1%, 0.063 W, AEC-Q200 Grade 0, 0402", Manufacturer=Vishay-Dale, Power_W=63mW, Supplier Part Number 1=541-49.9KLCT-ND, TempCo="100 ppm/C", Tolerance_%=1%, Value2=0.063W, Value_Code=49k9, ValueDisplayed=49.9k
R24 R112 R122: library part CMP-0025950-3, "RES, 100 k, 1%, 0.063 W, AEC-Q200 Grade 0, 0402", Manufacturer=Vishay-Dale, Power_W=63mW, Supplier Part Number 1=541-100KLCT-ND, TempCo="100 ppm/C", Tolerance_%=1%, Value2=0.063W, Value_Code=100k
R27: library part CMP-0078244-2, "RES, 30.0 k, 1%, 0.063 W, AEC-Q200 Grade 0, 0402", Manufacturer=Vishay-Dale, Power_W=63mW, Supplier Part Number 1=541-30.0KLCT-ND, TempCo="100 ppm/C", Tolerance_%=1%, Value2=0.063W, Value_Code=30k0, ValueDisplayed=30.0k
R39: library part CMP-0026993-2, "RES, 100, 5%, 0.1 W, AEC-Q200 Grade 0, 0402", Manufacturer=Panasonic, Power_W=100mW, Supplier Part Number 1=P100JCT-ND, TempCo="200 ppm/C", Tolerance_%=5%, Value2=0.1W, Value_Code=100R, ValueDisplayed=100
R64: library part CMP-0027745-1, "RES, 4.99 k, 1%, 0.05 W, 0201", Manufacturer="Yageo America", Power_W=50mW, Supplier Part Number 1=YAG2712CT-ND, TempCo="200 ppm/C", Tolerance_%=1%, Value2=0.05W, Value_Code=4k99, ValueDisplayed=4.99k
R68: library part CMP-0026404-2, "RES, 49.9, 1%, 0.063 W, AEC-Q200 Grade 0, 0402", Manufacturer=Vishay-Dale, Power_W=63mW, Supplier Part Number 1=541-49.9LCT-ND, TempCo="100 ppm/C", Tolerance_%=1%, Value2=0.063W, Value_Code=49R9, ValueDisplayed=49.9
R71: library part CMP-0027008-4, "RES, 0, 5%, 0.05 W, 0201", Manufacturer=Vishay-Dale, Power_W=50mW, Supplier Part Number 1=72M6743, TempCo=ppm/C, Tolerance_%=5%, Value2=0.05W, Value_Code=0000, ValueDisplayed=0
R72 R73 R74 R76 R89 R95: library part CMP-0026071-3, "RES, 1.00 k, 1%, 0.063 W, AEC-Q200 Grade 0, 0402", Manufacturer=Vishay-Dale, Power_W=63mW, Supplier Part Number 1=541-1.00KLCT-ND, TempCo="100 ppm/C", Tolerance_%=1%, Value2=0.063W, Value_Code=1k00, ValueDisplayed=1.00k
R75: library part CMP-0027052-1, "RES, 1.0 k, 5%, 0.05 W, 0201", Manufacturer="Yageo America", Power_W=50mW, Supplier Part Number 1=311-1KNCT-ND, TempCo="200 ppm/C", Tolerance_%=5%, Value2=0.05W, Value_Code=1k00, ValueDisplayed=1.0k
R87 R123: library part CMP-0025958-3, "RES, 10.0 k, 1%, 0.063 W, AEC-Q200 Grade 0, 0402", Manufacturer=Vishay-Dale, Power_W=63mW, Supplier Part Number 1=541-10.0KLCT-ND, TempCo="100 ppm/C", Tolerance_%=1%, Value2=0.063W, Value_Code=10k0, ValueDisplayed=10.0k
R90: library part CMP-0026413-2, "RES, 4.87 k, 1%, 0.063 W, AEC-Q200 Grade 0, 0402", Manufacturer=Vishay-Dale, Power_W=63mW, Supplier Part Number 1=541-4.87KLCT-ND, TempCo="100 ppm/C", Tolerance_%=1%, Value2=0.063W, Value_Code=4k87, ValueDisplayed=4.87k
R97: library part CMP-0001699-1, "10 kOhms ±1% 0.063W, 1/16W Chip Resistor 0402 (1005 Metric) Moisture Resistant Thick Film", Digikey Part Number=311-10.0KLRCT-ND, Manufacturer=Yageo, Mouser Part Number=603-RC0402FR-0710KL, Operating Temperature Range="-55°C to +155°C", Power_W=63mW, TempCo=100ppm/°C, Tolerance_%=1%
R104 R106: library part CMP-0078212-1, "RES, 510, 5%, 0.1 W, AEC-Q200 Grade 0, 0402", Manufacturer=Panasonic, Power_W=100mW, Supplier Part Number 1=P510JCT-ND, TempCo="200 ppm/C", Tolerance_%=5%, Value2=0.1W, Value_Code=510R, ValueDisplayed=510
R105 R107 R108: library part CMP-0027137-1, "RES, 510, 5%, 0.05 W, 0201", Manufacturer="Yageo America", Power_W=50mW, Supplier Part Number 1=YAG2907CT-ND, TempCo="200 ppm/C", Tolerance_%=5%, Value2=0.05W, Value_Code=510R, ValueDisplayed=510
R110: library part CMP-0026414-2, "RES, 4.99 k, 1%, 0.063 W, AEC-Q200 Grade 0, 0402", Manufacturer=Vishay-Dale, Power_W=63mW, Supplier Part Number 1=541-4.99KLCT-ND, TempCo="100 ppm/C", Tolerance_%=1%, Value2=0.063W, Value_Code=4k99, ValueDisplayed=4.99k
R113: library part CMP-0022735-3, "RES, 100 k, 1%, 0.1 W, 0603", Manufacturer="Yageo America", PartNumber=RC0603FR-07100KL, Power_W=100mW, Supplier Part Number 1=311-100KHRCT-ND, TempCo="200 ppm/C", Tolerance_%=1%, Value2=0.1W, Value_Code=100k
R114: library part CMP-0023142-5, "RES, 49.9 k, 1%, 0.1 W, 0603", Manufacturer=Yageo, PartNumber=RC0603FR-0749K9L, Power_W=100mW, Supplier Part Number 1=311-49.9KHRCT-ND, TempCo="100 ppm/C", Tolerance_%=1%, Value2=0.1W, Value_Code=49k9, ValueDisplayed=49.9k
R120: library part CMP-0091690-1, "RES 0 OHM JUMPER 1/4W 0603", Digikey Part Number=HCJ0603ZT0R00CT-ND, Manufacturer="Stackpole Electronics", Operating Temperature Range="-55°C to +155°C", Power_W=250mW
R139: library part CMP-0026299-2, "RES, 33.2, 1%, 0.063 W, AEC-Q200 Grade 0, 0402", Manufacturer=Vishay-Dale, Power_W=63mW, Supplier Part Number 1=541-33.2LCT-ND, TempCo="100 ppm/C", Tolerance_%=1%, Value2=0.063W, Value_Code=33R2, ValueDisplayed=33.2
R141: library part CMP-0026890-5, "RES, 2.2 k, 5%, 0.063 W, AEC-Q200 Grade 0, 0402", Manufacturer=Vishay-Dale, Power_W=63mW, Supplier Part Number 1=541-2.2KJCT-ND, TempCo="200 ppm/C", Tolerance_%=5%, Value2=0.063W, Value_Code=2k20, ValueDisplayed=2.2k
R158 R170 R172: library part CMP-0027891-1, "RES, 82.5 k, 1%, 0.05 W, 0201", Manufacturer="Yageo America", Power_W=50mW, Supplier Part Number 1=YAG2815CT-ND, TempCo="200 ppm/C", Tolerance_%=1%, Value2=0.05W, Value_Code=82k5, ValueDisplayed=82.5k
R159 R171: library part CMP-0027165-1, "RES, 750, 5%, 0.05 W, 0201", Manufacturer="Yageo America", Power_W=50mW, Supplier Part Number 1=YAG2927CT-ND, TempCo="200 ppm/C", Tolerance_%=5%, Value2=0.05W, Value_Code=750R, ValueDisplayed=750
S1: library part CMP-0002128-2, "Switch, Slide, SPST 4 poles, SMT", CurrentRating_mA=25A, Manufacturer="CTS Electrocomponents", Supplier Part Number 1=CT2184LPST-ND
S3: library part CMP-0087181-1, "SWITCH SLIDE DIP SPST 100MA 6V", Manufacturer="Nidec Copal Electronics"
SW2 SW3: library part CMP-0002150-2, "SWITCH TACTILE SPST-NO 0.05A 12V", CurrentRating_mA=50A, Manufacturer="Omron Electronic Components", Supplier Part Number 1=SW1020CT-ND
TP1 TP2 TP3 TP4 TP5 TP6 TP7 TP8 TP9 TP10 TP12 TP14 TP15 TP16 TP17 TP22 TP23 TP24: library part CMP-0078143-3, "TEST POINT.  No entry in BOM.", Manufacturer=N/A
TP11: library part CMP-0003825-1, "1mm Test Point, SMT", Manufacturer=Any
TP20: library part CMP-0086474-1, "PC Test Point, Loop Brass, Tin Plating 0.047\" (1.19mm) Hole Diameter Mounting Type", Manufacturer="Keystone Electronics"
U2: library part CMP-0860942-2, "XI6843ARQGALP, ALP0180A (BGA-180)", Alternate Manufacturer="Texas Instruments"
U4: library part CMP-0036402-3, "Single Output High PSRR LDO, 1 A, Adjustable 1.2 to 5.5 V Output, 2.7 to 5.5 V Input, 8-pin SON (DRB), -40 to 125 degC, Green (RoHS & no Sb/Br)", Manufacturer="Texas Instruments"
U5: library part CMP-0029856-2, "Tiva C Series Microcontroller, 1024 KB Flash, 256 KB SRAM, 12 Bit, 20 Channels, -40 to 105 degC, 128-Pin TQFP (PDT), Green (RoHS & no Sb/Br), Tray", Manufacturer="Texas Instruments", Temperature Range="-40 to 105 degC"
U6: library part CMP-0033001-1, "Precision Micropower Shunt Voltage Reference, 0.5% accuracy, 2.5 V, 15 ppm / degC, 15 mA, -40 to 125 degC, 3-pin SOT-23 (DBZ), Green (RoHS & no Sb/Br)", Manufacturer="Texas Instruments", Rating=Catalog, Temp Coeff(Max)(ppm/ degree C)=100, Temp Coeff(Typ)(ppm/ degree C)=15
U8: library part CMP-0096220-1, "3.5V to 65V Synchronous Step-Down Voltage Regulator", Manufacturer="Texas Instruments", Operating Temperature Range=to
U9: library part CMP-0078466-1, "ULTRA LOW POWER, 16M-BIT [x 1/x 2/x 4] CMOS MXSMIO (SERIAL MULTI I/O) FLASH MEMORY, SON-8", Manufacturer="Macronix International Co., LTD", Supplier Part Number 1=1092-1178-1-ND
U10: library part CMP-0091078-3, "Three Buck Converters and 5-V Boost for AWR and IWR Radar Sensors", Manufacturer="Texas Instruments", Max Supply Voltage=4V, Min Supply Voltage=3V, Nominal Supply Current=3uA, Operating Temperature Range="-40°C to +150°C", Output Voltage=0.9-1.9V, Switching Frequency=4.4-8.8-17.6MHz
U16: library part CMP-0087998-2, "AND Gate IC 1 Channel  6-SON (1x1)", Digikey Part Number=296-30121-1-ND, Manufacturer="Texas Instruments", Max Supply Voltage=5.5V, Min Supply Voltage=1.65V, Mouser Part Number=595-SN74LVC1G11DSFR, Operating Temperature Range="-40°C to +125°C"
Y1: library part CMP-0087164-1, "CRYSTAL 40.0000MHZ 8PF SMD", Frequency_Fixed=40MHz, Frequency Stability=15ppm, Load Capacitance=8pF, Manufacturer="Kyocera International Inc. Electronic Components"
Y2: library part CMP-0095014-1, "16 MHz ±15ppm Crystal 8pF 80 Ohms 4-SMD, No Lead", Digikey Part Number=50-ECS-160-8-33Q-RES-CT-ND, Frequency Stability=50ppm, Frequency Tolerance=15ppm, Frequency_Fixed=16MHz, Load Capacitance=8pF, Manufacturer=ECS, Mouser Part Number=520-ECS160833QRES-TR, Operating Temperature Range="-40°C to +125°C"
Y4: library part CMP-0088006-1, "CRYSTAL 32.768KHZ 4PF SMD", Frequency_Fixed=32.768kHz, Frequency Tolerance=20ppm, Load Capacitance=4pF, Manufacturer="Abracon LLC"
ZZ1: library part CMP-0003616-3
ZZ2: library part CMP-0077236-1
ZZ3: library part CMP-0077237-1
ZZ4 ZZ5.2: library part CMP-0077238-1
ZZ5.1: library part CMP-0077238-1, "Cut the thermal pad(Part Number#GPVOUS-0.125-AC-0816) for the shape and size of the inner surface of the heatsink(Part Number#160018120021) and paste it on the inner surface of the heatsink;"

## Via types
v1: diameter 18, hole 8, Top Layer to Bottom Layer, tented both sides, 533 vias
v2: diameter 19.68, hole 7.87, Top Layer to Bottom Layer, 5 vias
v3: diameter 17, hole 8, Top Layer to Bottom Layer, tented both sides, 1 vias

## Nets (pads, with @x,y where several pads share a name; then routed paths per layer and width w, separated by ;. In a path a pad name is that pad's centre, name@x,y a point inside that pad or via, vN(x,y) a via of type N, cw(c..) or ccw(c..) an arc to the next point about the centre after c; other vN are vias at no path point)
3V3_LDO_EN: R18.2 R24.2 U4.8 | length 109.2
  Top Layer w15: U4.8@5520.53,4017.97 5561.26,4017.97 ; R18.2@5561.26,4068.79 5561.26,4017.97 ; R24.2@5562.22,4000.76 5561.26,4001.72 5561.26,4017.97
5V_IN: C1.2 C4.1 C118.2 C127.2 D1.1 L1.1 R1.1 R64.1 R105.1 R107.1 | length 3823.1
  Top Layer w20: v1(2326.55,3943.25) 2326.82,3942.98 R105.1@2358.26,3942.98 2363.17,3947.89 2389.06,3947.89 C1.2@2391.06,3949.89 ; R107.1@5490.33,4385.7 5490.33,4153.84 R1.1@5491.22,4152.95
  PWR2 w20: v1(2798.85,3820.87) 3535.84,3820.87 3633.17,3918.2 3816.78,3918.2 3895.2,3996.63 4189.92,3996.63 4201.64,4008.34 4201.64,4082.39 4230.25,4111 5389.68,4111 v1(5491.92,4213.24)
  Bottom Layer w10: v1(2399.98,4041.01) 2401.51,4042.54 2401.51,4059.34 2409.74,4067.58 2409.74,4068.37 2411.04,4069.66 R64.1@2411.83,4069.66
  Bottom Layer w20: v1(2326.55,3943.25) 2326.78,3943.02 2326.78,3868.12 2464.37,3730.53 2732.2,3730.53 2738.05,3736.39 C118.2@2738.05,3780
  other v1: 2722.9,3820.87 2749.18,3820.87 2774.04,3820.87 2369.7,4013.73 2399.98,4014.03 2370.9,4040.71
AGND: C48.1 C49.1 C108.1 NT1.1 NT2.1 NT3.1 NT4.2 U10.5 U10.5-19 U10.19 | length 332.1
  Top Layer w10: C48.1@3045.13,3980.41 3045.13,4012.04 ; C49.1@3045.13,4041.76 3045.13,4012.04 ; U10.19@3187.98,4012.04 3166.79,4012.04 3166.36,4012.47 3105.96,4012.47 3105.53,4012.04 3045.13,4012.04 ; U10.5@3348.33,4012.04 3424.72,4012.04 3439.17,4026.49 C108.1@3442.7,4026.49
  GND1 w8: NT2.1@3197.01,4007.12 3201.12,4011.23 v1(3222.53,4011.23)
  other v1: 3239.18,3983.13 3300.16,3982.76 3244.16,4012.04 3304.06,4012.04 3325.69,4012.85 3238.48,4040.1 3303.75,4040.32
  other v2: 3271.56,4012.04
AR_1P0_RF2: C70.1 C73.1 C74.1 C75.1 C76.1 C78.1 C79.1 C80.1 C81.1 C82.1 C83.1 C84.1 C85.1 C86.2 C93.2 L9.2 R126.2 U2.G16 U2.G17 U2.G18 U2.H16 U2.H17 U2.H18 U2.J16 U2.J17 U2.J18 | length 1694.8
  Top Layer w10: v1(3092.74,3683.4) 3091.85,3684.29 3091.85,3704.76 v1(3090.96,3705.65) 3133.23,3705.65 C86.2@3135.22,3707.64 ; v1(3100.8,3731.5) 3100.81,3754.33 3107.62,3761.14 L9.2@3125.31,3761.14 ; C93.2@3134.6,3663.53 3128.77,3657.7 v1(3092.36,3657.7) 3090.84,3656.19 3090.84,3635.7 3095.67,3630.87 v1(3095.67,3628.71) 3095.86,3628.52 3123.33,3628.52 v1(3123.52,3628.32) 3123.78,3628.58 3146.54,3628.58 v1(3146.8,3628.83) ; v1(3961.99,4362.62) 3961.99,4362.35 3977.74,4346.6 U2.G16@3977.74,4346.33 ; v1(3961.99,4393.58) U2.G17@3977.74,4377.83 ; v1(3961.99,4425.07) U2.G18@3977.74,4409.33 ; v1(3993.49,4362.53) 3993.49,4362.31 4009.24,4346.56 U2.H16@4009.24,4346.33 ; v1(3993.49,4393.58) U2.H17@4009.24,4377.83 ; v1(3993.49,4425.07) U2.H18@4009.24,4409.33 ; U2.J16@4040.73,4346.33 4040.73,4346.52 4056.48,4362.27 v1(4056.48,4362.45) ; U2.J17@4040.73,4377.83 v1(4056.48,4393.58) ; U2.J18@4040.73,4409.33 v1(4056.48,4425.07)
  Sig2 w4.2: v1(3079.9,3782.09) 3157.56,3782.09 3340.29,3964.82 3340.29,4086.62 3508.7,4255.03 3886.99,4255.03 v1(3916.06,4284.1)
  Bottom Layer w8: v1(3079.9,3782.09) 3081.81,3780.18 3119.5,3780.18 R126.2@3124.79,3774.89
  Bottom Layer w10: v1(4056.48,4362.45) 4056.48,4360.28 4058.77,4357.99 4058.77,4345.16 4058.9,4345.04 C78.1@4058.9,4317.13 ; v1(4056.48,4393.58) 4058.01,4392.05 4058.01,4382.08 4060.26,4379.83 4060.26,4379.05 4061.56,4377.75 C80.1@4062.35,4377.75 ; v1(4056.48,4425.07) 4058.01,4423.54 4058.01,4412.2 4058.77,4411.45 4058.77,4410.66 4060.07,4409.36 C81.1@4060.85,4409.36 ; C79.1@4060.2,4346.34 C79.1@4060.86,4346.34
  other v1: 3938.08,4284.1 3958.01,4284.1 3941.08,4304.27 3963.26,4304.27 3987.33,4304.27
AR_1P2: C91.1 C92.1 C94.1 C95.1 C96.1 C97.1 C98.1 C99.2 C103.1 C104.2 L10.2 R128.2 U2.A5 U2.C1 U2.E1 U2.J1 U2.V4 U2.V6 U2.V7 U2.V8 U2.V12 U2.V14 U2.V15 | length 2275.2
  Top Layer w10: v1(3073.24,4354.19) 3075.4,4354.19 3081.11,4348.49 C99.2@3106.76,4348.49
  Top Layer w15: v1(3073.67,4289.87) 3074.49,4289.87 3079.95,4284.41 3093.68,4284.41 3094.66,4285.38 3102.47,4285.38 3109.73,4292.65 3109.73,4298.55 3088.63,4319.65 3074.68,4319.65 v1(3074.11,4320.22) ; U2.A5@3788.76,3999.88 v1(3804.51,4015.63) ; v1(3836.01,3858.15) U2.C1@3851.76,3873.89 ; v1(3899.61,3855.87) 3899.61,3857.31 3914.75,3872.45 U2.E1@3914.75,3873.89 ; U2.J1@4040.84,3873.78 v1(4056.59,3858.04) ; v1(4308.45,3984.13) U2.V4@4324.2,3968.38 ; U2.V6@4324.2,4031.37 v1@4339.94,4015.63 ; U2.V7@4324.2,4062.87 4324.34,4063.01 4331.43,4063.01 4341.37,4072.96 v1@4341.37,4083.04 ; U2.V8@4324.2,4094.37 4324.34,4094.22 4324.54,4094.22 4336.83,4081.94 4340.56,4081.94 v1@4341.37,4082.75 ; U2.V12@4324.2,4220.35 4335.73,4231.88 4367.79,4231.88 4374.94,4224.73 C96.1@4388.37,4224.73 v1@4388.37,4205.15 ; U2.V14@4324.2,4283.34 4324.2,4285.59 4338.42,4285.59 4352,4299.17 ; U2.V15@4324.2,4314.84 4336.34,4314.84 4352,4299.17 ; v1(4367.19,4204.15) 4367.76,4203.57 4369.89,4203.57 4370.5,4202.96 4386.19,4202.96 4387.9,4204.66 v1(4388.71,4204.66) ; v1(4419.9,4285.71) 4398.91,4306.69 4389.67,4306.69 4388.37,4307.99 C98.1@4388.37,4308.78 4361.61,4308.78 4352,4299.17
  Sig1 w15: v1(3071.07,4151.88) 3108.04,4151.88 3181.31,4078.62 3736.21,4078.62 3798.63,4016.2 3803.94,4016.2 v1(3804.51,4015.63) ; v1(4388.71,4204.66) 4411.54,4204.66 4419.45,4196.75 4452.77,4196.75 4461.55,4205.53 4461.55,4265.94 4441.79,4285.71 v1(4419.9,4285.71)
  Sig2 w15: v1(3071.07,4151.88) v1(3071.07,4262.98) ; v1(4056.59,3858.04) 4056.59,3890.96 4081.01,3915.38 4136.72,3915.38 4150.97,3901.14 4225.46,3901.14 v1(4308.45,3984.13)
  Bottom Layer w10: v1(3071.07,4262.98) 3072.6,4261.45 3084.43,4261.45 3115.49,4230.39 R128.2@3115.49,4228.42 ; v1@3803.34,4015.63 v1(3804.51,4015.63)
  Bottom Layer w15: C97.1@3779.79,4039.17 v1@3803.34,4015.63 ; v1(3899.61,3855.87) 3916.58,3872.84 3916.58,3874.15 3922.37,3879.94 C95.1@3922.37,3880.73 ; v1(4056.59,3858.04) 4056.59,3858.85 4065.74,3868 C92.1@4065.74,3873.08 ; C91.1@4303,4035.17 4321.4,4035.17 v1(4340.94,4015.63) ; C103.1@4303,4058.8 4305.12,4056.68 4318.19,4056.68 4340.8,4079.29 4340.8,4080.79 v1(4341.37,4081.36) ; C94.1@4304.21,3964.68 4304.21,3979.89 v1(4308.45,3984.13)
AR_1V4_APLL: C90.1 U2.A10 | length 62.3
  Top Layer w10: C90.1@3737.06,4182.85 3763.27,4182.85 U2.A10@3788.76,4157.36
AR_1V4_SYNTH: C89.1 U2.A9 | length 55.5
  Top Layer w10: C89.1@3737.19,4135.45 3779.18,4135.45 U2.A9@3788.76,4125.86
